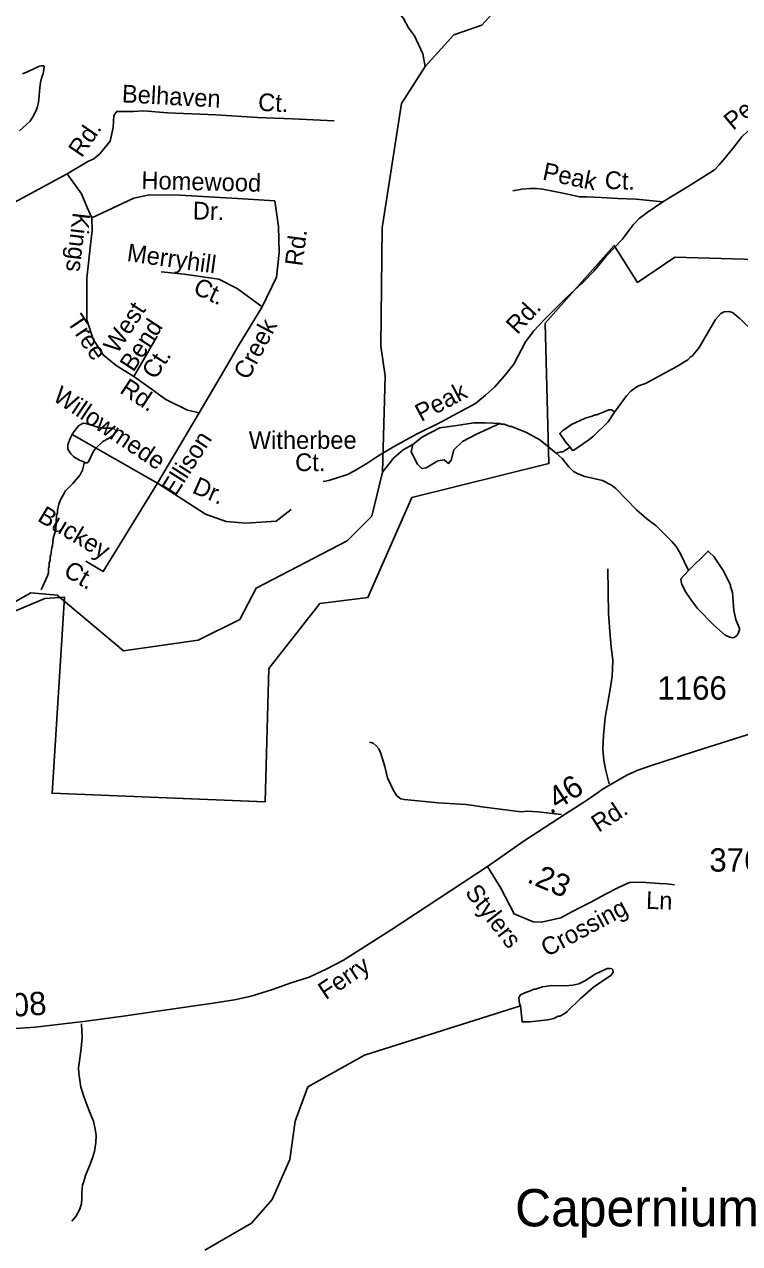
# Model space of a CAD drawing. Extents: x 1547597 to 1699558, y 810033 to 920809.
# Drawn here: x 1576579 to 1580417, y 841689 to 848225 of the extents above; entities that cross this region are included whole.
import ezdxf

# ---------------------------------------------------------------- set-up
doc = ezdxf.new("R2010")
doc.units = 0
for name, color, linetype in [('Exist Boundary Political City Limit New', 7, 'Continuous'), ('Exist Civil Demographics Community Label', 7, 'Continuous'), ('Exist Hydrographic Creek Single Shore', 7, 'Continuous'), ('Exist Hydrographic Misc Water Feature', 7, 'Continuous'), ('Exist Road Non-System Type 51', 7, 'Continuous'), ('Exist Road Non-System Type 51 Label', 7, 'Continuous'), ('Exist Road Secondary Mileage Hundredths English Label', 7, 'Continuous'), ('Exist Road Secondary Type 51 Attributed', 7, 'Continuous'), ('Exist Road Secondary Type 51 Label', 7, 'Continuous'), ('Exist Road Secondary Type 51 Number Label', 7, 'Continuous'), ('Map Preparation Boundary City Limit Buffer Line', 7, 'Continuous')]:
    doc.layers.add(name, color=color, linetype=linetype)

msp = doc.modelspace()

# ---------------------------------------------------------------- linework, layer by layer
at = {"layer": 'Exist Boundary Political City Limit New'}
for points in [[(1580998, 846949.9), (1580069.5, 846978), (1579869.4, 846842.4), (1579743.6, 847039.3), (1579374, 846624.2), (1579393.8, 845870.5), (1578657.8, 845689), (1578422.2, 845152.2), (1578164.4, 845120.5), (1577890.8, 844771.6)], [(1577890.8, 844771.6), (1577871, 844057.5), (1576728.2, 844103.8), (1576794.3, 845155), (1576688.6, 845148.4), (1576424.4, 845036)]]:
    msp.add_lwpolyline(points, dxfattribs=at)
at = {"layer": 'Exist Hydrographic Creek Single Shore'}
msp.add_lwpolyline([(1576336.5, 845023.4), (1576613.5, 845178.7), (1576755.5, 845165.9), (1577111.2, 844866.3), (1577511, 844923.5), (1577734.3, 845034.4), (1577822.5, 845203.4), (1578311.6, 845457.4), (1578443.1, 845589), (1578500.2, 845824.6), (1578514.5, 846341.6), (1578491.6, 846499.7), (1578498.3, 847135.3), (1578602.5, 847800.7), (1578730.1, 847999.7), (1578883.7, 848168.6), (1579034.3, 848220.6), (1579141.6, 848338.4)], dxfattribs=at)
at = {"layer": 'Exist Hydrographic Misc Water Feature'}
for points in [[(1578565.9, 848315.6), (1578613.1, 848256.2), (1578640.6, 848207.8), (1578672.1, 848163.4), (1578716.9, 848067), (1578730.1, 847999.7)], [(1576569.1, 847961), (1576600, 847972.7), (1576632.9, 847989.4), (1576655.8, 848000), (1576669.4, 848003.5), (1576682.9, 848003.2), (1576685.2, 848000.1), (1576683.8, 847982.9), (1576679.7, 847962.1), (1576670.7, 847937.1), (1576665.4, 847914.4), (1576661.9, 847886.2), (1576658.1, 847843.9), (1576654.3, 847805.9), (1576650.3, 847784.5), (1576641.9, 847763.1), (1576624.8, 847729.7), (1576610.2, 847707.2), (1576591.4, 847687.9), (1576553.4, 847654.8)], [(1580737.7, 846317.2), (1580712.2, 846352.6), (1580686.4, 846376.9), (1580645.1, 846429.4), (1580562, 846502.4), (1580562.2, 846507.8), (1580420.1, 846646.9), (1580377.6, 846681.5), (1580358.8, 846685.5), (1580334.2, 846685.2), (1580316.1, 846675.4), (1580287.7, 846643.8), (1580199.9, 846493), (1580161.4, 846447.5), (1580153.3, 846443.6), (1580139.1, 846427.8), (1580079.8, 846391.5), (1579911.7, 846300.7), (1579873.5, 846287.2), (1579849.4, 846271.5), (1579831.2, 846257.7), (1579808.9, 846234), (1579745.1, 846146.6)], [(1579507.3, 845958.6), (1579482.1, 845988.3), (1579451.4, 846032.8), (1579458.7, 846038.5), (1579466.8, 846046.4), (1579515.2, 846079.8), (1579587.6, 846114.9), (1579625.7, 846124.4), (1579641.8, 846132.1), (1579649.8, 846132), (1579714.1, 846159.3), (1579730.1, 846159.1), (1579745.1, 846146.6)], [(1579745.1, 846146.6), (1579711.3, 846095.3), (1579632.4, 846018.3), (1579608.2, 845998.7), (1579527.6, 845943.7), (1579519.5, 845941.8), (1579507.3, 845958.6)], [(1576901.5, 845878.9), (1576907.2, 845874.7), (1576915.2, 845874.5), (1576923.3, 845880.4), (1576950, 845938.1), (1576962.2, 845954), (1577000.6, 845989.4), (1577034.8, 846007), (1577059.1, 846024.7), (1577069.2, 846040.5), (1577069.3, 846048.5), (1577059.4, 846058.7), (1577053.4, 846060.7), (1577001.4, 846061.4), (1576973.6, 846065.8), (1576909.8, 846086.5), (1576893.8, 846086.7), (1576869.6, 846073), (1576839.1, 846033.5), (1576822.8, 846001.7), (1576812.5, 845971.8), (1576812.2, 845947.8), (1576827.9, 845923.7), (1576843.7, 845907.5), (1576875.4, 845889.1), (1576901.5, 845878.9)], [(1578662.9, 845973.6), (1578654.3, 845933.8), (1578688.9, 845867.9), (1578711.4, 845845.4), (1578735.6, 845848.9), (1578797.9, 845885.3), (1578830.8, 845890.5), (1578855.1, 845871.4), (1578868.9, 845888.7), (1578882.8, 845944.2), (1578929.5, 845989.2), (1579005.6, 846029.1), (1579129.4, 846086.6)], [(1578662.9, 845973.6), (1578714.9, 846015.2), (1578808.3, 846062), (1578900.1, 846075.8), (1578990.1, 846089.7), (1579048.9, 846089.7), (1579093.1, 846087.1)], [(1579432.7, 845925.9), (1579344.3, 845997.9), (1579272.7, 846036.8), (1579193.1, 846069.8), (1579185.1, 846069.9), (1579153.3, 846082.3), (1579137.3, 846082.5), (1579129.4, 846086.6), (1579093.1, 846087.1)], [(1578500.2, 845824.6), (1578560.8, 845902.6), (1578611, 845944.2), (1578662.9, 845973.6)], [(1579507.3, 845958.6), (1579467.4, 845934.4), (1579459.4, 845934.5), (1579432.7, 845925.9)], [(1580141.7, 845298.3), (1580096.9, 845390.8), (1580075.3, 845427), (1580053.6, 845453.3), (1579966.6, 845538.3), (1579919.1, 845574.9), (1579863.7, 845623.6), (1579753, 845737), (1579729.2, 845755.2), (1579681.6, 845779.8), (1579585.8, 845801), (1579544.1, 845817.5), (1579524.2, 845829.8), (1579500.5, 845854), (1579465, 845898.5), (1579432.7, 845925.9)], [(1576901.5, 845878.9), (1576890.8, 845834.9), (1576878.5, 845811), (1576840, 845763.6), (1576799.5, 845724.1), (1576772.9, 845676.4), (1576764.7, 845652.5), (1576756.3, 845620.6), (1576756.1, 845604.7), (1576752, 845596.8), (1576747.1, 845516.8), (1576734.5, 845469), (1576730.1, 845429.1), (1576726, 845421.1), (1576721.4, 845381.2), (1576717.3, 845373.2), (1576717, 845349.3), (1576712.9, 845341.3), (1576712.7, 845317.4), (1576708.6, 845309.4), (1576708.3, 845285.4), (1576704.1, 845269.5), (1576670, 845193.4)], [(1580141.7, 845298.3), (1580101.2, 845252.8), (1580103.1, 845238.7), (1580106.9, 845222.7), (1580128.4, 845182.4), (1580153.9, 845142.2), (1580191.3, 845093.7), (1580278.3, 845004.7), (1580339.6, 844951.9), (1580363.5, 844939.6), (1580379.5, 844937.4), (1580387.5, 844939.3), (1580401.5, 844949.1), (1580407.7, 844957), (1580415.9, 844978.9), (1580416, 844986.9), (1580396.6, 845035.2), (1580385.1, 845083.3), (1580378.3, 845179.3), (1580366.7, 845211.5), (1580366.8, 845219.5), (1580331.6, 845291.8), (1580278.6, 845372.5), (1580254.9, 845394.8), (1580247.6, 845401.5), (1580240.9, 845394.9), (1580141.7, 845298.3)], [(1579241.7, 842963.4), (1579240.3, 842966.6), (1579236.4, 842974.7), (1579232.7, 843006.7), (1579234.9, 843014.6), (1579240.9, 843022.6), (1579267.1, 843036.2), (1579289.2, 843042), (1579313.3, 843053.6), (1579321.3, 843053.5), (1579359.4, 843065.1), (1579409.5, 843072.5), (1579481.4, 843071.5), (1579521.5, 843075), (1579553.6, 843082.6), (1579585.8, 843098.2), (1579642.2, 843133.5), (1579706.5, 843164.7), (1579722.5, 843164.5), (1579730.5, 843162.4), (1579736.4, 843156.3), (1579738.3, 843144.3), (1579728.1, 843128.4), (1579633.4, 843063.6), (1579560.6, 843000.6), (1579491.8, 842933.5), (1579475.7, 842921.6), (1579451.5, 842908), (1579443.5, 842908.1), (1579419.4, 842896.4), (1579387.3, 842888.8), (1579291.3, 842878), (1579259.3, 842878.4), (1579249.2, 842878.5), (1579247.5, 842898.5), (1579241.7, 842963.4)], [(1577546.5, 841653.8), (1577798.5, 841799.7), (1577908.5, 841925.5), (1578003.5, 842140.2), (1578031.5, 842346.5), (1578100.5, 842528.9), (1578403.5, 842700), (1579241.7, 842963.4)]]:
    msp.add_lwpolyline(points, dxfattribs=at)
at = {"layer": 'Exist Road Non-System Type 51'}
for p, q in [((1577166.3, 846337), (1577291.5, 846554)), ((1577517.7, 846142.4), (1577293.2, 845765.2))]:
    msp.add_line(p, q, dxfattribs=at)
for points in [[(1581391.3, 847692.3), (1581011.6, 847819.8), (1580942.8, 847837.7), (1580907.1, 847842.8), (1580866.3, 847847.9), (1580789.9, 847842.8), (1580747.6, 847836.6), (1580675.2, 847807.6), (1580600.6, 847760.7), (1580533.9, 847717.6), (1580489.3, 847680.1), (1580428.5, 847622.9), (1580385.6, 847567.5), (1580338.8, 847510.3), (1580306.2, 847472.7), (1580281.8, 847445), (1580146.6, 847359.1), (1580005.2, 847274.9)], [(1576809.5, 847424.2), (1576920.5, 847489.6), (1576951.1, 847505.3), (1576983.4, 847532.3), (1577007.7, 847559.3), (1577040, 847599.7), (1577056.2, 847672.5), (1577058.9, 847737.3), (1577075.1, 847758.8), (1577123.6, 847758.8), (1577164, 847758.8), (1577220.6, 847761.5), (1577347.3, 847750.7), (1577606, 847740), (1577829.7, 847726.5), (1578018.4, 847718.4), (1578242.1, 847707.6)], [(1576809.5, 847424.2), (1576505.6, 847260.4)], [(1576809.5, 847424.2), (1576884.8, 847317.1), (1576916.5, 847243.7), (1576940.3, 847188.2)], [(1576940.3, 847188.2), (1577166.2, 847293.3), (1577251.4, 847311.1), (1577413.9, 847309.1), (1577723, 847291.3), (1577923.1, 847279.4)], [(1580005.2, 847274.9), (1579861.5, 847289), (1579763.5, 847292.4), (1579673.5, 847297.8), (1579595.5, 847301), (1579557.5, 847301.6), (1579495.6, 847314.4), (1579405.9, 847333.6), (1579359.8, 847342.4), (1579325.9, 847344.9), (1579291.9, 847345.4), (1579248, 847342), (1579199.8, 847332.6)], [(1577923.1, 847279.4), (1577942.9, 847142.6), (1577946.9, 847001.8), (1577931.1, 846870.9), (1577855.8, 846711)], [(1580005.2, 847274.9), (1579920.4, 847216.2), (1579878, 847184.8), (1579845.5, 847151.2), (1579786.2, 847072), (1579701, 846983.3), (1579692.6, 846973.1), (1579635.7, 846904.1), (1579574.8, 846840.9), (1579485.5, 846760.3), (1579363.8, 846637.9), (1579312.8, 846582.7), (1579268, 846523.4), (1579204.4, 846404.2), (1579155.3, 846340.8), (1579102.4, 846281.6), (1579053.7, 846238.4), (1578999.2, 846193), (1578902.3, 846140.4), (1578813.7, 846093.7), (1578682.7, 846029.5), (1578559.6, 845961.4), (1578474.8, 845910.5), (1578416.1, 845871.3), (1578349.5, 845832.2), (1578313.3, 845812.7), (1578263.1, 845795.5), (1578212.8, 845780.3), (1578182.7, 845774.7)], [(1577166.3, 846337), (1577071.2, 846396.5), (1577001.8, 846454), (1576948.3, 846537.3), (1576914.7, 846642.4), (1576914.7, 846735.6), (1576914.7, 846864.5), (1576936.4, 847059.7), (1576942.4, 847119.2), (1576940.3, 847188.2)], [(1577855.8, 846711), (1577721.1, 846810.2), (1577622, 846859.8), (1577435.7, 846885.6), (1577312.9, 846899.4)], [(1577855.8, 846711), (1577727, 846500.8), (1577665.7, 846394.5), (1577517.7, 846142.4)], [(1577517.7, 846142.4), (1577453.6, 846156.5), (1577338.7, 846214.1), (1577259.4, 846271.6), (1577166.3, 846337)], [(1577293.2, 845765.2), (1576835.4, 846026.9)], [(1577293.2, 845765.2), (1577001.6, 845292.1), (1576908.1, 845347.7)], [(1577293.2, 845765.2), (1577550.8, 845600.6), (1577661.7, 845560.9), (1577766.8, 845551), (1577929.3, 845562.9), (1578010.5, 845624.4)], [(1579715.8, 844154.8), (1579697.1, 844232), (1579687.9, 844280.2), (1579682.7, 844340.4), (1579685.8, 844414.3), (1579695.1, 844510.2), (1579714.7, 844619.9), (1579725.6, 844683.9), (1579732.4, 844731.8), (1579734.8, 844769.7), (1579735.5, 844815.7), (1579726.6, 844888), (1579719.8, 844970), (1579713.2, 845068.1), (1579708.6, 845306.4)], [(1579460.1, 843990), (1579334.7, 844004.6), (1579276.3, 844007.5), (1579245.6, 844004.4), (1579215.6, 844006.8), (1579047.8, 844029.4), (1578950, 844042.8), (1578800.1, 844052.9), (1578618.2, 844069.5), (1578598.3, 844073.9), (1578576.6, 844090.2), (1578558.9, 844118.4), (1578527.9, 844186.8), (1578512.7, 844247.2), (1578491.7, 844317.4), (1578480, 844341.7), (1578466.3, 844358), (1578450.6, 844372.1), (1578430.5, 844378.3)], [(1576885.7, 842866.8), (1576888.7, 842796.7), (1576883.7, 842736.8), (1576874.7, 842668.9), (1576870.1, 842631), (1576871.7, 842601), (1576877.2, 842564.8), (1576882.7, 842528.7), (1576900, 842472.5), (1576915.3, 842430.2), (1576932.7, 842388), (1576950.2, 842345.6), (1576959.6, 842303.6), (1576965.1, 842269.5), (1576962.5, 842231.5), (1576955.7, 842183.6), (1576943.1, 842143.6), (1576928.7, 842105.9), (1576907.9, 842054.1), (1576897.4, 842022.3), (1576891.2, 842002.4), (1576886.7, 841966.5), (1576888.2, 841930.4), (1576885.6, 841904.5), (1576877.2, 841874.6), (1576854.6, 841834.9), (1576834.3, 841809.1)]]:
    msp.add_lwpolyline(points, dxfattribs=at)
at = {"layer": 'Exist Road Secondary Type 51 Attributed'}
for points in [[(1581329.1, 844691.9), (1580388.3, 844395), (1580180.4, 844329.4), (1580004.2, 844272.6), (1579937.7, 844250.8), (1579869.8, 844227.4), (1579811.7, 844200.6), (1579685.3, 844126.8), (1579605.5, 844072.2), (1579480.4, 843990.7), (1579260.5, 843848.6), (1579063.3, 843710.5)], [(1579063.3, 843710.5), (1578547.9, 843370.9), (1578292, 843208), (1578198.2, 843161.2), (1578107.8, 843117.5), (1578009.9, 843087.8), (1577910.1, 843050.7), (1577795.2, 843016.1), (1577705.8, 842996.7), (1577591.9, 842977.9), (1577318.1, 842938.6), (1577108.9, 842909.3), (1576910.7, 842882), (1576636.3, 842850.3), (1576423.7, 842836)], [(1579063.3, 843710.5), (1579135.5, 843595.1), (1579206.4, 843457.3), (1579308.6, 843413.5), (1579354.4, 843412), (1579457.2, 843436.5), (1579517.2, 843467.1), (1579565.5, 843492.7), (1579613.8, 843518.5), (1579697.1, 843562.6), (1579766.8, 843598.1), (1579825.5, 843625.1), (1579887.9, 843627.5), (1579985.8, 843619), (1580023.8, 843617.7), (1580067.8, 843612.8)]]:
    msp.add_lwpolyline(points, dxfattribs=at)
at = {"layer": 'Map Preparation Boundary City Limit Buffer Line'}
for points in [[(1580998, 846949.9), (1580069.5, 846978), (1579869.4, 846842.4), (1579743.6, 847039.3), (1579374, 846624.2), (1579393.8, 845870.5), (1578657.8, 845689), (1578422.2, 845152.2), (1578164.4, 845120.5), (1577890.8, 844771.6)], [(1577890.8, 844771.6), (1577871, 844057.5), (1576728.2, 844103.8), (1576794.3, 845155), (1576688.6, 845148.4), (1576424.4, 845036)]]:
    msp.add_lwpolyline(points, dxfattribs=at)

# ---------------------------------------------------------------- texts
at = {"layer": 'Exist Civil Demographics Community Label'}
msp.add_text('Capernium', height=200, dxfattribs=at).set_placement((1579211.8, 841781.6))
at = {"layer": 'Exist Road Non-System Type 51 Label'}
for s, rotation, p in [('Belhaven', 356.86572, (1577100.6, 847807.8)), ('Peak', 40.05753, (1580381.6, 847653.8)), ('Ct.', 357.45176, (1577831.7, 847762)), ('Rd.', 55.61634, (1576886.6, 847506.4)), ('Homewood', 358.62426, (1577206.1, 847343.2)), ('Peak', 348.31796, (1579354.2, 847393.9)), ('Ct.', 358.01172, (1579691.7, 847344.1)), ('Dr.', 358.62426, (1577481.9, 847180)), ('Kings', 263.25831, (1576839.6, 847220.1)), ('Rd.', 82.33692, (1578070.4, 846925.7)), ('Merryhill', 352.00969, (1577125.6, 846956.8)), ('Ct.', 335.21352, (1577478.6, 846785.7)), ('West', 57.00358, (1577076.8, 846454.6)), ('Rd.', 47.26446, (1579223.7, 846558.8)), ('Tree', 303.87093, (1576804.2, 846631.4)), ('Bend', 57.00358, (1577164.1, 846357.1)), ('Creek', 62.30829, (1577780.4, 846314.1)), ('Ct.', 57.00358, (1577282.5, 846316.6)), ('Rd.', 326.39068, (1577085.2, 846254.2)), ('Willowmede', 326.12368, (1576725.6, 846213.8)), ('Peak', 27.79316, (1578707.5, 846093.3)), ('Witherbee', 0.087, (1577782.9, 845949.1)), ('Ellison', 57.50086, (1577388.5, 845689.4)), ('Ct.', 359.75465, (1578031.7, 845830.9)), ('Dr.', 336.35458, (1577474.4, 845716.5)), ('Buckey', 329.30136, (1576643.8, 845566.7)), ('Ct.', 329.30136, (1576782.8, 845274.3))]:
    msp.add_text(s, height=95, rotation=rotation, dxfattribs=at).set_placement(p)
at = {"layer": 'Exist Road Secondary Mileage Hundredths English Label'}
for s, height, rotation, p in [('.46', 120, 33.17688, (1579402.2, 843988.3)), ('.23', 120, 336.78187, (1579270.4, 843629)), ('1.08', 125, 3.8487, (1576376.7, 842895.5))]:
    msp.add_text(s, height=height, rotation=rotation, dxfattribs=at).set_placement(p)
at = {"layer": 'Exist Road Secondary Type 51 Label'}
for s, rotation, p in [('Rd.', 32.90324, (1579660.1, 843890.7)), ('Stylers ', 307.85117, (1578939.9, 843570)), ('Ln', 358.15081, (1579913.5, 843483.9)), ('Crossing', 28.12956, (1579382.9, 843224.2)), ('Ferry', 33.85689, (1578195.8, 842993.2))]:
    msp.add_text(s, height=95, rotation=rotation, dxfattribs=at).set_placement(p)
at = {"layer": 'Exist Road Secondary Type 51 Number Label'}
for s, p in [('1166', (1579975.6, 844605.4)), ('3763', (1580254.2, 843683.5))]:
    msp.add_text(s, height=125, dxfattribs=at).set_placement(p)

doc.saveas('drawing.dxf')
